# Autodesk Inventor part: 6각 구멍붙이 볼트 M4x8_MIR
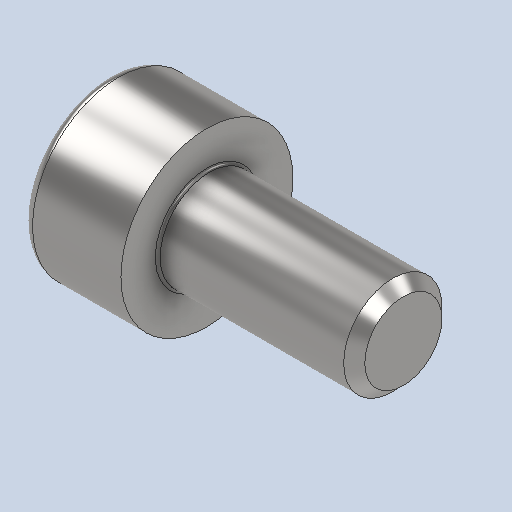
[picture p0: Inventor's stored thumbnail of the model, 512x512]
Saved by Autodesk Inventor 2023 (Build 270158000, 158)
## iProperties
Created: 2026-06
Part Number: 6각 구멍붙이 볼트 M4x8_MIR
Material: 강철, 연강
Description: 6각머리 태핑 나사
Document SubType Name: Modeling
Designer: home
Density: 7.85 g/cm^3
Appearance: 기본값
Author: jhkim
Sending System: Autodesk Inventor 2027
Preprocessor: ST-DEVELOPER v20.1
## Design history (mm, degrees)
derived "6각 구멍붙이 볼트 M4x8.ipt"
feature "솔리드1::6각 구멍붙이 볼트 M4x8.ipt" dims "d0" = 10
tag "피쳐 태그1"
node "솔리드1"
